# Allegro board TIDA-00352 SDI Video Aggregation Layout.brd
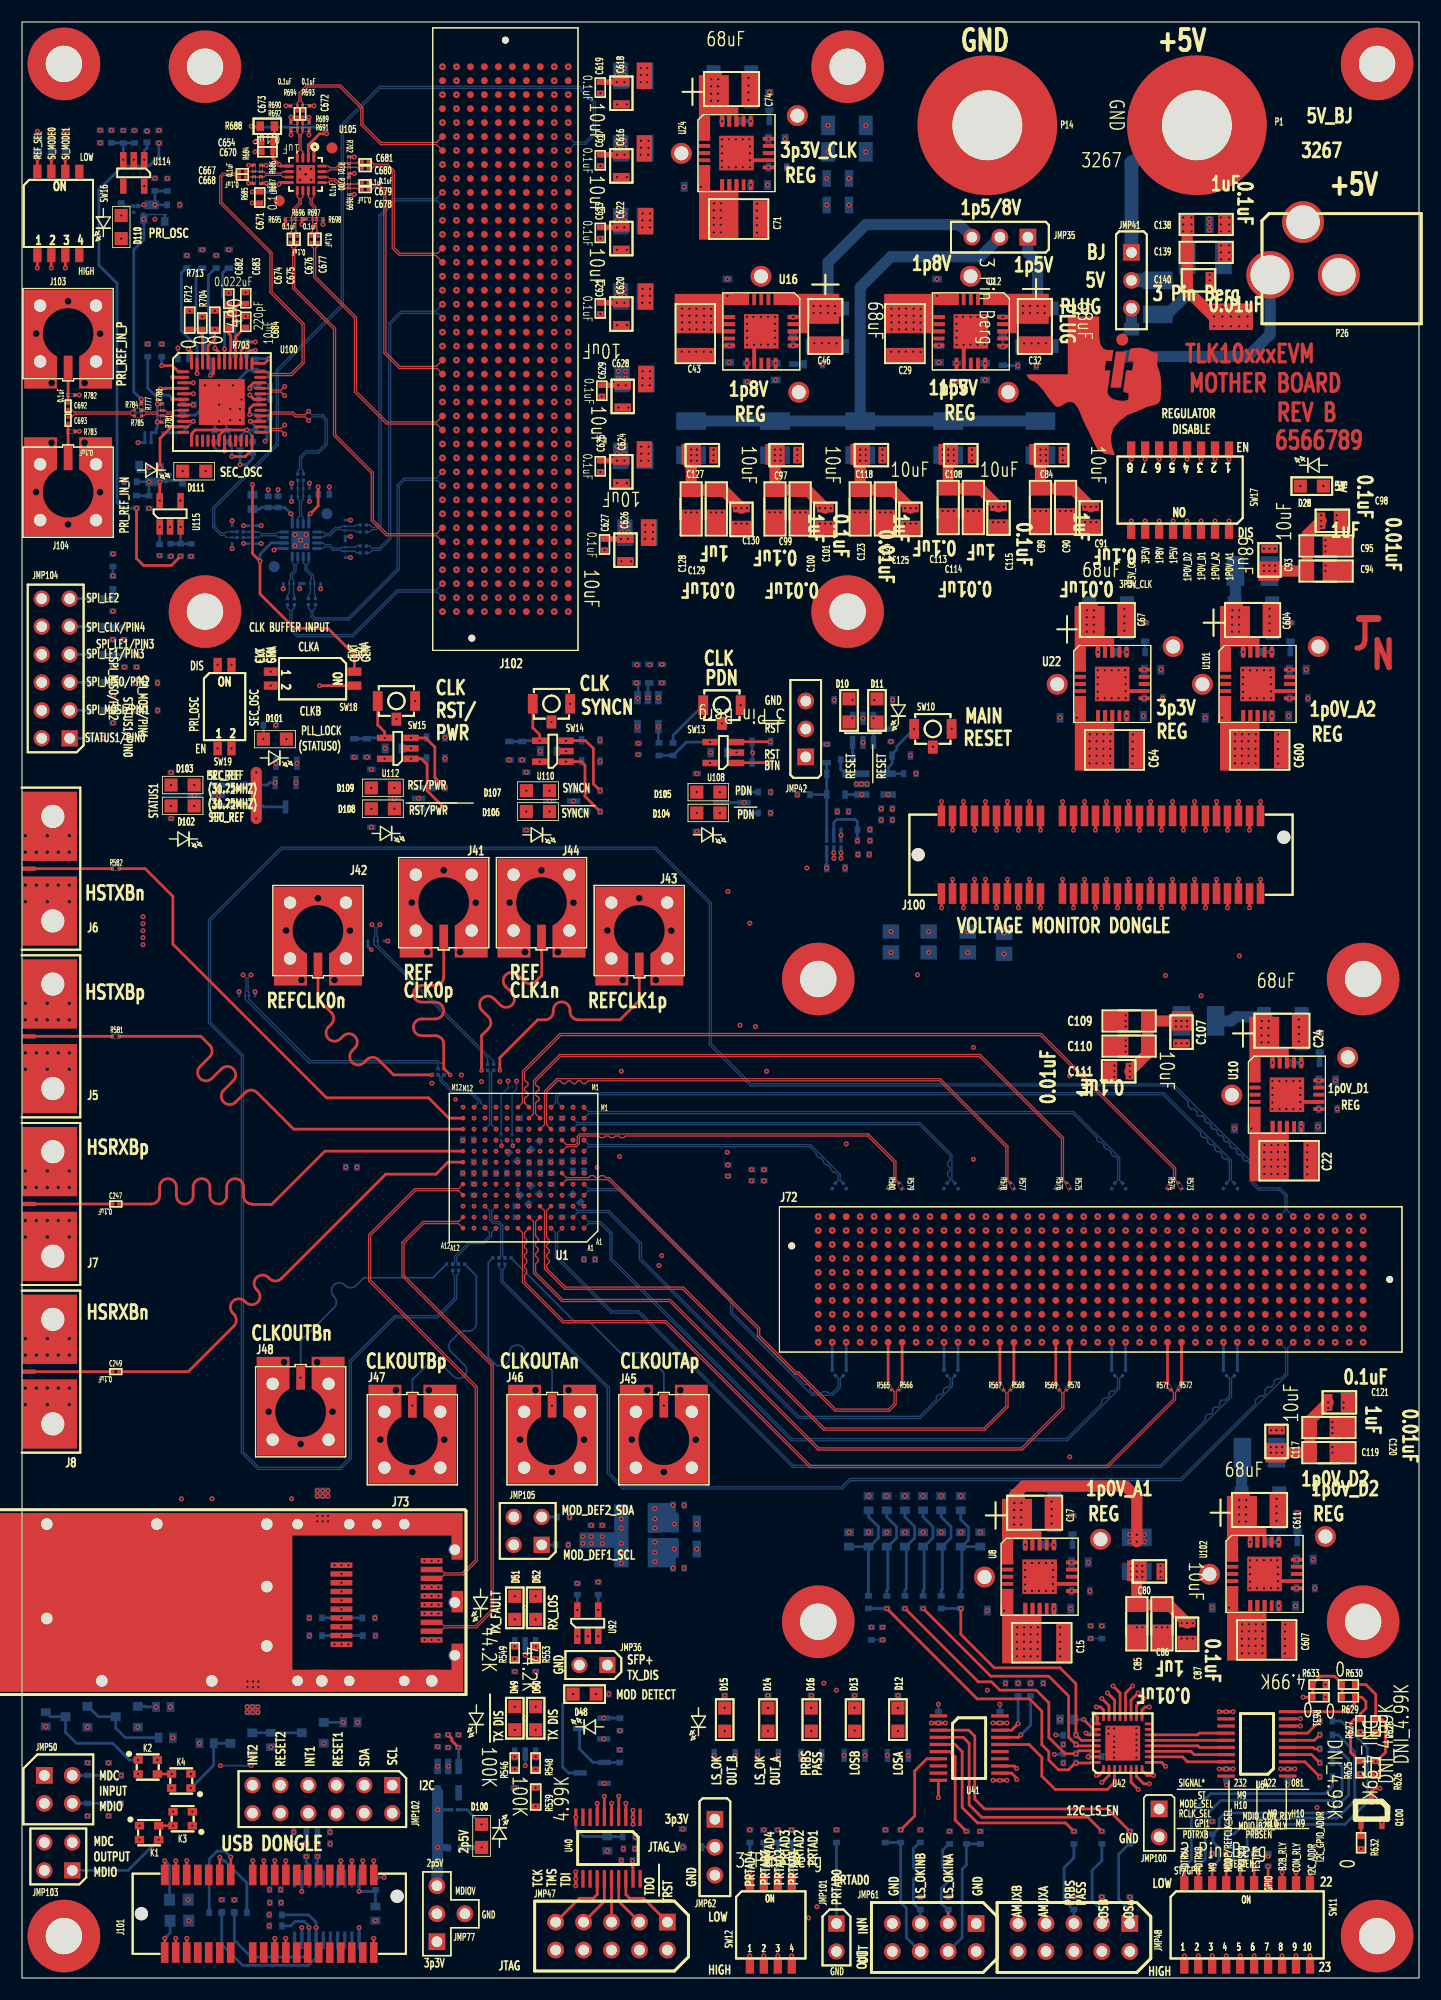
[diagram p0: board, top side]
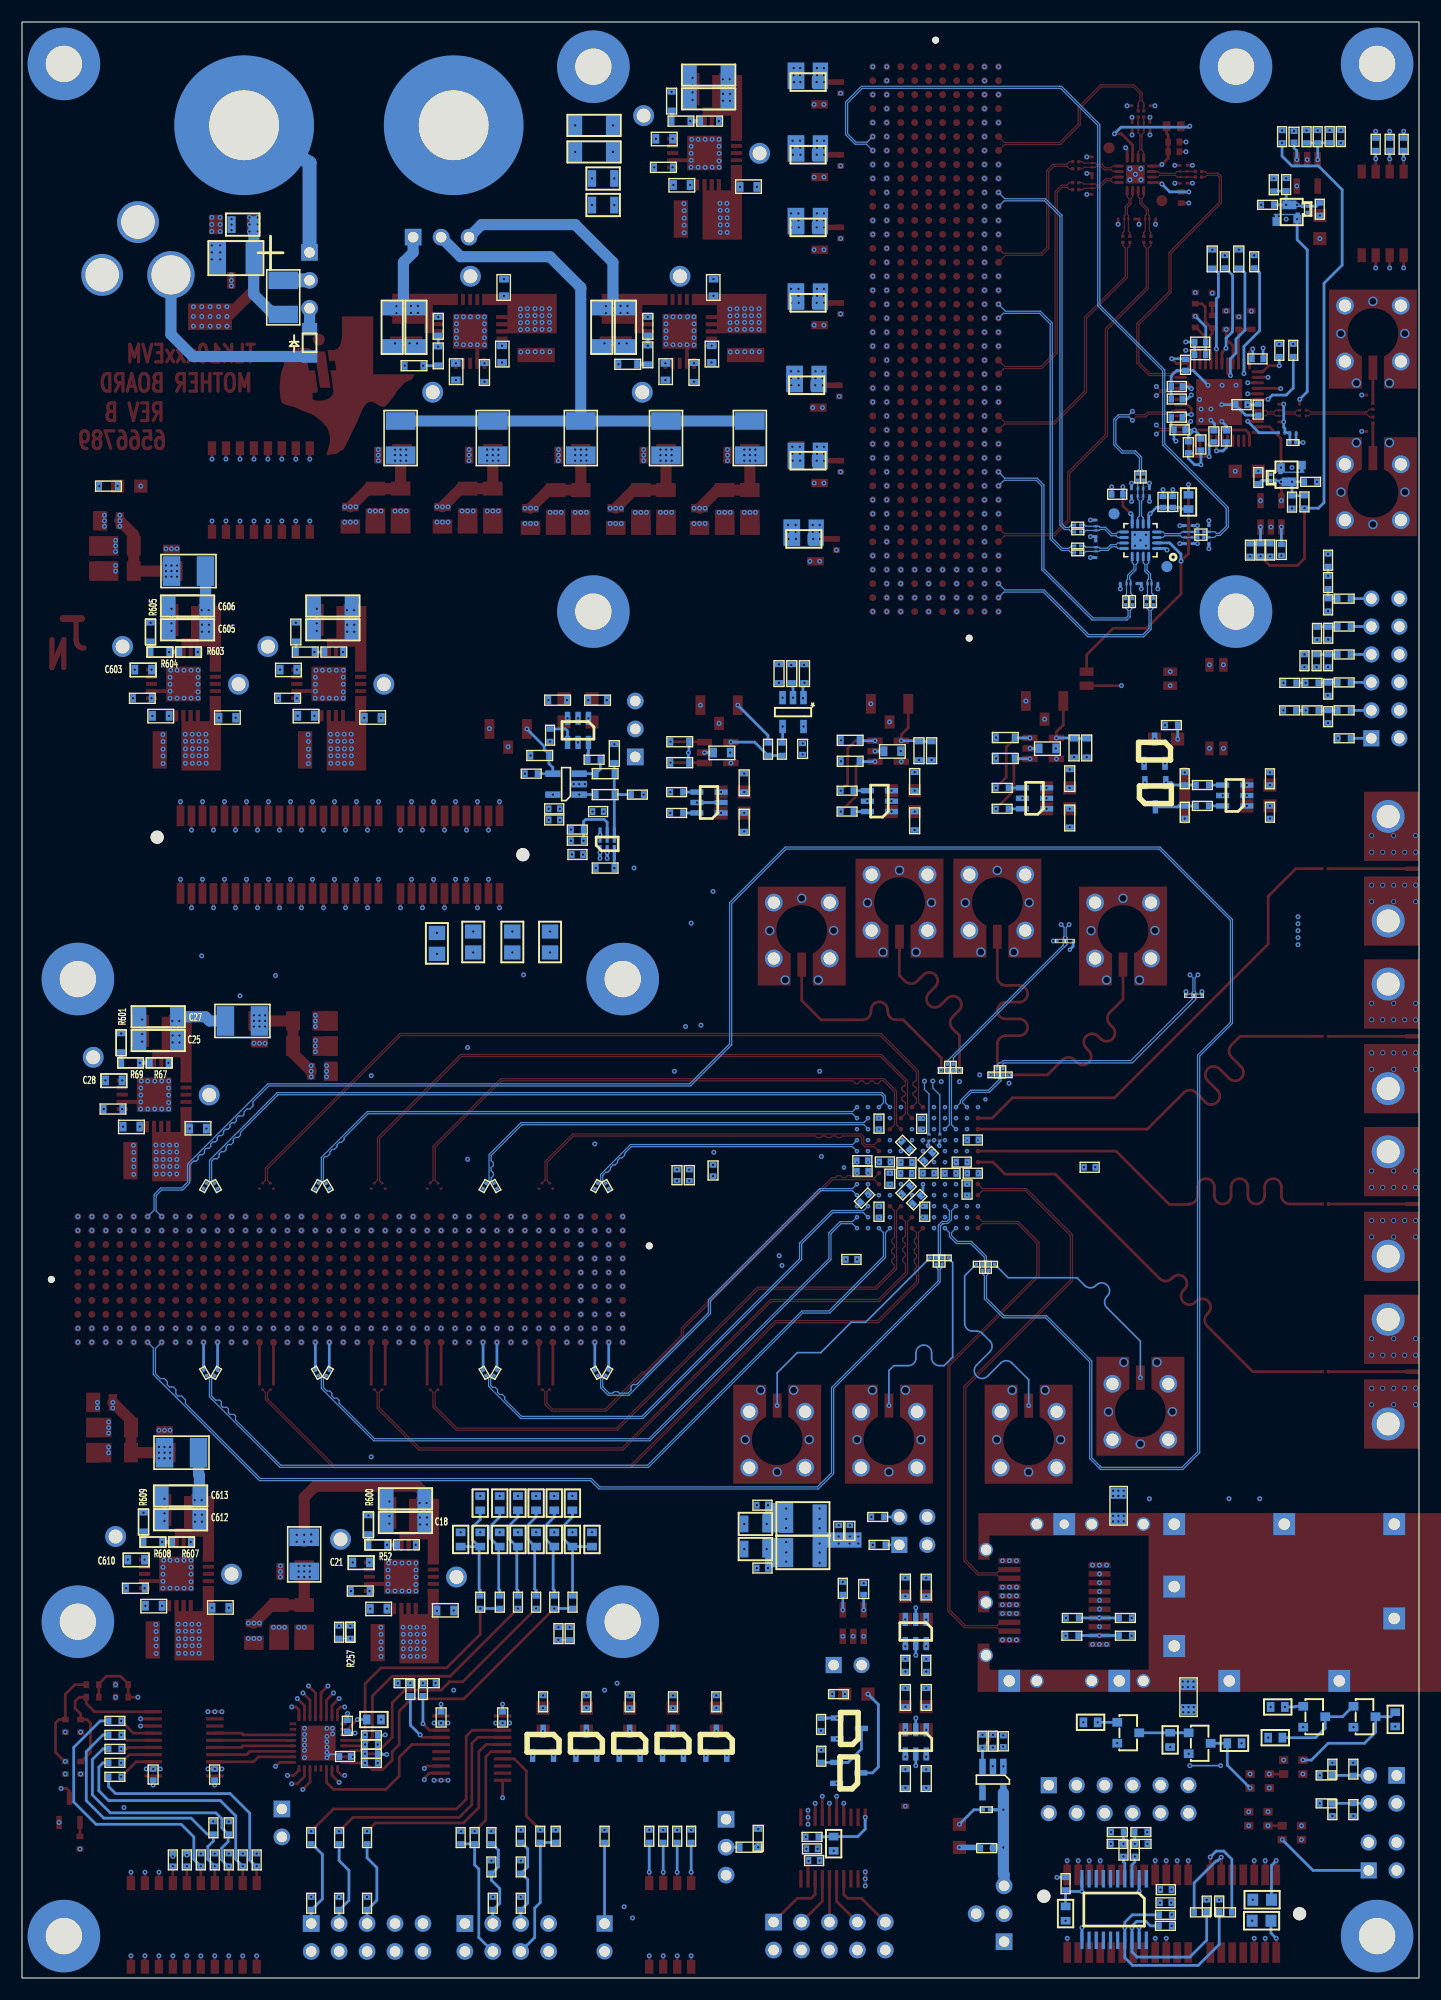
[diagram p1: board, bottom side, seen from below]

Outline 127 x 177.8 mm; copper layers: TOP, L2_GND, L3_SIG2, L4_GND, L5_PWR, L6_GND, L7_GND, L8_PWR, L9_GND, L10_PWR, L11_GND, L12_PWR, L13_GND, L14_SIG3, L15_GND, BOTTOM. Coordinates in mm from the lower left corner of the outline.
Outline path: rectangle 0,0 127,177.8

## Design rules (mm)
net group DIFF_CHA_CLKOUT_CONN: nets CHA_CLKOUTN_CONNECTOR CHA_CLKOUTP_CONNECTOR
net group DIFF_CLK0: nets REFCLK0N REFCLK0P
net group DIFF_CLK1: nets REFCLK1N REFCLK1P
net group DIFF_CLK_IN: nets CLKA_IN_N0 CLKA_IN_P0
net group DIFF_CLKA0: nets CLKA0N CLKA0P
net group DIFF_CLKA0_CON: nets CLKA0N_CON CLKA0P_CON
net group DIFF_CLKA1: nets CLKA1N CLKA1P
net group DIFF_CLKA1_CON: nets CLKA1N_CON CLKA1P_CON
net group DIFF_CLKA1_IN_CON: nets CLKA1N_IN_CON CLKA1P_IN_CON
net group DIFF_CLKA2: nets CLKA2N CLKA2P
net group DIFF_CLKA2_CON: nets CLKA2N_CON CLKA2P_CON
net group DIFF_CLKA3: nets CLKA3N CLKA3P
net group DIFF_CLKA_IN: nets CLKA_IN_N1 CLKA_IN_P1
net group DIFF_CLKA_IN_Y5: nets CLKA_IN_N_Y5N CLKA_IN_P_Y5P
net group DIFF_CLKB0: nets CLKB0N CLKB0P
net group DIFF_CLKB0N_CON: nets CLKB0N_CON CLKB0P_CON
net group DIFF_CLKB1: nets CLKB1N CLKB1P
net group DIFF_CLKB1_CON: nets CLKB1N_CON CLKB1P_CON
net group DIFF_CLKB1_IN_CON: nets CLKB1N_IN_CON CLKB1P_IN_CON
net group DIFF_CLKB2: nets CLKB2N CLKB2P
net group DIFF_CLKB2_CON: nets CLKB2N_CON CLKB2P_CON
net group DIFF_CLKB3: nets CLKB3N CLKB3P
net group DIFF_CLKB3N_CON: nets CLKA3N_CON CLKA3P_CON
net group DIFF_CLKB_IN: nets CLKB_IN_N1 CLKB_IN_P1
net group DIFF_CLKB_IN_Y7: nets CLKB_IN_N_Y7N CLKB_IN_P_Y7P
net group DIFF_CLKOUTA: nets CLKOUTAN CLKOUTAP
net group DIFF_CLKOUTB: nets CLKOUTBN CLKOUTBP
net group DIFF_DP1: nets CLKB3N_CON CLKB3P_CON
net group DIFF_INA0: nets INA0N INA0P
net group DIFF_INA1: nets INA1N INA1P
net group DIFF_INA2: nets INA2N INA2P
net group DIFF_INA3: nets INA3N INA3P
net group DIFF_INB0: nets A4N A4P
net group DIFF_INB1: nets A5N A5P
net group DIFF_INB2: nets A6N A6P
net group DIFF_INB3: nets A7N A7P
net group DIFF_JC_CLK0: nets REFCLK0N_U0N REFCLK0P_U0P
net group DIFF_JCCLK1: nets REFCLK1N_U1N REFCLK1P_U1P
net group DIFF_OUTA0: nets OUTA0N OUTA0P
net group DIFF_OUTA1: nets OUTA1N OUTA1P
net group DIFF_OUTA2: nets OUTA2N OUTA2P
net group DIFF_OUTA3: nets OUTA3N OUTA3P
net group DIFF_OUTB0: nets OUTA4N OUTA4P
net group DIFF_OUTB1: nets OUTA5N OUTA5P
net group DIFF_OUTB2: nets OUTA6N OUTA6P
net group DIFF_OUTB3: nets OUTA7N OUTA7P
net group DIFF_PRI_REF: nets PRI_REFN PRI_REFP
net group DIFF_PRI_REF_IN: nets PRI_REF_IN_N PRI_REF_IN_P
net group HSRXA: nets HSRXAN HSRXAP
net group HSTXA: nets HSTXAN HSTXAP
net group HIGH_SPEED: nets HSRXBN HSRXBP HSTXBN HSTXBP
net group HIGH_SPEED_SMA: nets HSRXBN_SMA HSRXBP_SMA HSTXBN_SMA HSTXBP_SMA
net group REFCLK_SMP: nets CLKOUTAN_SMA CLKOUTAP_SMA CLKOUTBN_SMA CLKOUTBP_SMA REFCLK0N_SMP REFCLK0P_SMP REFCLK1N_SMP REFCLK1P_SMP

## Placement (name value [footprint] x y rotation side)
C15  100uF  [CC1812]  92.71 30.48 0 top
C16  4.7uF  [CC0603]  89.28 33.4 180 bottom
C17  68uF  [CC1210]  90.42 42.29 0 top
C18  10uF  [CC1206]  90.42 41.4 0 bottom
C19  1uF  [CC0603]  93.81 33.57 0 bottom
C20  1uF  [CC1206]  90.42 43.56 0 bottom
C21  0.001uF  [CC0603]  95.41 37.77 0 bottom
C22  100uF  [CC1812]  115.19 74.3 0 top
C23  4.7uF  [CC0603]  111.76 77.22 180 bottom
C24  68uF  [CC1210]  112.9 86.11 0 top
C25  10uF  [CC1206]  112.9 85.22 0 bottom
C26  1uF  [CC0603]  116.29 77.39 0 bottom
C27  1uF  [CC1206]  112.9 87.38 0 bottom
C28  0.001uF  [CC0603]  117.89 81.59 0 bottom
C29  100uF  [CC1812]  80.26 149.48 270 top
C30  4.7uF  [CC0603]  83.19 152.91 90 bottom
C31  1uF  [CC0603]  83.36 148.38 270 bottom
C32  68uF  [CC1210]  92.08 151.76 270 top
C33  10uF  [CC1206]  91.19 151.76 270 bottom
C34  1uF  [CC1206]  93.34 151.76 270 bottom
C35  0.015uF  [CC0603]  87.56 146.78 270 bottom
C43  100uF  [CC1812]  61.21 149.48 270 top
C44  4.7uF  [CC0603]  64.14 152.91 90 bottom
C45  1uF  [CC0603]  64.31 148.38 270 bottom
C46  68uF  [CC1210]  73.03 151.76 270 top
C47  10uF  [CC1206]  72.14 151.76 270 bottom
C48  1uF  [CC1206]  74.3 151.76 270 bottom
C49  0.015uF  [CC0603]  68.51 146.78 270 bottom
C64  100uF  [CC1812]  99.31 111.63 0 top
C65  4.7uF  [CC0603]  95.89 114.55 180 bottom
C66  1uF  [CC0603]  100.42 114.73 0 bottom
C67  68uF  [CC1210]  97.03 123.44 0 top
C68  10uF  [CC1206]  97.03 122.56 0 bottom
C69  1uF  [CC1206]  97.03 124.71 0 bottom
C70  10pF  [CC0603]  102.02 118.93 0 bottom
C71  100uF  [CC1812]  65.15 159.89 0 top
C72  4.7uF  [CC0603]  61.72 162.81 180 bottom
C73  1uF  [CC0603]  66.25 162.99 0 bottom
C74  68uF  [CC1210]  62.87 171.7 0 top
C75  10uF  [CC1206]  62.87 170.81 0 bottom
C76  1uF  [CC1206]  62.87 172.97 0 bottom
C77  10pF  [CC0603]  67.85 167.19 0 bottom
C80  10uF  [CC0805]  101.47 36.96 0 top
C84  10uF  [CC0805]  92.58 138.43 0 top
C85  1uF  [CC1206]  101.35 33.91 270 top
C86  0.1uF  [CC1206]  103.63 33.91 270 top
C87  0.01uF  [CC0805]  105.92 32.26 270 top
C89  1uF  [CC1206]  92.58 135.38 270 top
C90  0.1uF  [CC1206]  94.87 135.38 270 top
C91  0.01uF  [CC0805]  97.16 133.73 270 top
C93  10uF  [CC0805]  113.41 127.89 90 top
C94  1uF  [CC1206]  116.84 127.89 0 top
C95  0.1uF  [CC1206]  116.84 130.18 0 top
C97  10uF  [CC0805]  68.45 138.43 0 top
C98  0.01uF  [CC0805]  118.11 132.46 0 top
C99  1uF  [CC1206]  68.45 135.25 270 top
C100  0.1uF  [CC1206]  70.74 135.25 270 top
C101  0.01uF  [CC0805]  73.03 133.6 270 top
C107  10uF  [CC0805]  105.41 87 270 top
C108  10uF  [CC0805]  84.33 138.43 0 top
C109  1uF  [CC1206]  102.36 87 180 top
C110  0.1uF  [CC1206]  102.36 84.71 180 top
C111  0.01uF  [CC0805]  100.71 82.42 180 top
C113  1uF  [CC1206]  84.2 135.38 270 top
C114  0.1uF  [CC1206]  86.49 135.38 270 top
C115  0.01uF  [CC0805]  88.77 133.73 270 top
C117  10uF  [CC0805]  114.05 47.75 90 top
C118  10uF  [CC0805]  76.2 138.43 0 top
C119  1uF  [CC1206]  117.09 47.75 0 top
C120  0.1uF  [CC1206]  117.09 50.04 0 top
C121  0.01uF  [CC0805]  118.75 52.32 0 top
C123  1uF  [CC1206]  76.2 135.25 270 top
C124  0.1uF  [CC1206]  78.49 135.25 270 top
C125  0.01uF  [CC0805]  80.77 133.6 270 top
C127  10uF  [CC0805]  60.83 138.43 0 top
C128  1uF  [CC1206]  60.83 135.25 270 top
C129  0.1uF  [CC1206]  63.12 135.25 270 top
C130  0.01uF  [CC0805]  65.41 133.6 270 top
C136  68uF  [CC1210]  105.92 156.34 0 bottom
C137  10uF  [CC0805]  105.92 159.38 0 bottom
C138  1uF  [CC1206]  105.94 159.4 0 top
C139  0.1uF  [CC1206]  105.94 156.86 0 top
C140  0.01uF  [CC0805]  105.94 154.32 0 top
C141  0.1uF  [CC0402]  41.12 73.18 180 bottom
C142  0.1uF  [CC0402]  42.13 74.18 180 bottom
C143  0.1uF  [CC0402]  49.99 71.27 315 bottom
C144  0.1uF  [CC0402]  50.05 74.27 0 bottom
C145  0.1uF  [CC0402]  50.03 73.32 0 bottom
C146  0.1uF  [CC0402]  64.16 73.96 270 bottom
C147  0.1uF  [CC0402]  44.91 70.21 270 bottom
C148  0.1uF  [CC0402]  45.24 77.09 90 bottom
C149  0.1uF  [CC0402]  30.5 73.71 180 bottom
C150  0.1uF  [CC0402]  49.08 70.21 270 bottom
C151  0.1uF  [CC0402]  48 74.16 0 bottom
C152  0.1uF  [CC0402]  48.09 73.21 270 bottom
C153  0.1uF  [CC0402]  43.15 73.16 180 bottom
C163  0.1uF  [CC0402]  41.07 72.22 270 bottom
C164  0.1uF  [CC0402]  46.28 75.28 45 bottom
C165  0.1uF  [CC0402]  44.21 75.04 315 bottom
C166  0.1uF  [CC0402]  46.06 73.12 0 bottom
C167  0.1uF  [CC0402]  46.22 72.03 315 bottom
C168  0.1uF  [CC0402]  52.15 65.33 180 bottom
C169  0.1uF  [CC0402]  49.11 77.11 90 bottom
C170  0.1uF  [CC0402]  45.14 73.18 180 bottom
C171  0.1uF  [CC0402]  46.04 74.11 0 bottom
C172  0.1uF  [CC0402]  45.25 71.13 315 bottom
C173  0.1uF  [CC0402]  66.32 73.53 270 bottom
C174  0.1uF  [CC0402]  67.44 73.53 270 bottom
C188  0.1uF  [CC0402]  41.12 76.19 180 bottom
C189  0.1uF  [CC0402]  79.17 106.3 180 bottom
C190  1uF  [CC0402]  79.17 105.28 180 bottom
C191  DNI_0.1uF  [CC0201]  38.36 82.09 0 bottom
C192  0.1uF  [CC0201]  43.9 65.46 0 bottom
C193  0.1uF  [CC0201]  38.36 82.66 270 bottom
C194  DNI_0.1uF  [CC0201]  43.9 65.46 270 bottom
C195  0.1uF  [CC0201]  37.82 82.66 270 bottom
C196  DNI_0.1uF  [CC0201]  43.36 65.46 270 bottom
C197  DNI_0.1uF  [CC0201]  37.82 82.09 180 bottom
C198  0.1uF  [CC0201]  43.36 65.46 180 bottom
C199  0.1uF  [CC0201]  42.87 82.5 0 bottom
C200  0.1uF  [CC0201]  39.69 64.89 0 bottom
C201  DNI_0.1uF  [CC0201]  42.87 83.06 270 bottom
C202  DNI_0.1uF  [CC0201]  39.69 64.89 270 bottom
C203  DNI_0.1uF  [CC0201]  42.33 83.06 270 bottom
C204  DNI_0.1uF  [CC0201]  39.15 64.89 270 bottom
C205  0.1uF  [CC0201]  42.33 82.5 180 bottom
C206  0.1uF  [CC0201]  39.15 64.89 180 bottom
C210  0.1uF  [CC0201]  74.65 54.76 60 bottom
C211  0.1uF  [CC0201]  109.5 72.24 240 bottom
C212  0.1uF  [CC0201]  73.94 54.76 120 bottom
C213  0.1uF  [CC0201]  110.21 72.24 300 bottom
C214  0.1uF  [CC0201]  84.81 54.76 60 bottom
C215  0.1uF  [CC0201]  99.34 72.24 240 bottom
C216  0.1uF  [CC0201]  84.1 54.76 120 bottom
C217  0.1uF  [CC0201]  100.05 72.24 300 bottom
C218  0.1uF  [CC0201]  100.05 54.76 60 bottom
C219  0.1uF  [CC0201]  84.1 72.24 240 bottom
C220  0.1uF  [CC0201]  99.34 54.76 120 bottom
C221  0.1uF  [CC0201]  84.81 72.24 300 bottom
C222  0.1uF  [CC0201]  110.21 54.76 60 bottom
C223  0.1uF  [CC0201]  73.94 72.24 240 bottom
C224  0.1uF  [CC0201]  109.5 54.76 120 bottom
C225  0.1uF  [CC0201]  74.65 72.24 300 bottom
C247  0.1uF  [CC0201]  8.8 70.36 180 top
C249  0.1uF  [CC0201]  8.8 55.12 180 top
C274  1uF  [CC0402]  115.06 19.05 270 bottom
C275  1uF  [CC0402]  109.47 19.05 270 bottom
C278  1uF  [CC0402]  88.92 23.12 90 bottom
C279  1uF  [CC0402]  83.32 23.12 90 bottom
C280  1uF  [CC0402]  97.44 22.37 90 bottom
C281  1uF  [CC0402]  97.07 20.12 0 bottom
C282  1uF  [CC0402]  75.95 102.11 0 bottom
C283  1uF  [CC0402]  75.18 106.05 180 bottom
C286  1uF  [CC0402]  23.57 8.05 180 bottom
C295  0.1uF  [CC0402]  52.77 40.08 90 bottom
C296  22uF  [CC0805]  59.31 41.27 0 bottom
C297  0.1uF  [CC0402]  59.13 42.96 0 bottom
C298  0.1uF  [CC0402]  50.5 34.8 90 bottom
C299  0.1uF  [CC0402]  51.76 40.08 90 bottom
C300  22uF  [CC0805]  59.31 38.99 0 bottom
C301  0.1uF  [CC0402]  59.13 37.25 0 bottom
C302  1uF  [CC0402]  23.6 6.86 180 bottom
C303  1uF  [CC0402]  55.55 10.69 180 bottom
C304  1uF  [CC0402]  55.74 11.76 180 bottom
C600  100uF  [CC1812]  112.52 111.63 0 top
C601  4.7uF  [CC0603]  109.09 114.55 180 bottom
C602  1uF  [CC0603]  113.62 114.73 0 bottom
C603  0.001uF  [CC0603]  115.22 118.93 0 bottom
C604  68uF  [CC1210]  110.24 123.44 0 top
C605  10uF  [CC1206]  110.24 122.56 0 bottom
C606  1uF  [CC1206]  110.24 124.71 0 bottom
C607  100uF  [CC1812]  113.16 30.73 0 top
C608  4.7uF  [CC0603]  109.73 33.66 180 bottom
C609  1uF  [CC0603]  114.26 33.83 0 bottom
C610  0.001uF  [CC0603]  115.86 38.03 0 bottom
C611  68uF  [CC1210]  110.87 42.55 0 top
C612  10uF  [CC1206]  110.87 41.66 0 bottom
C613  1uF  [CC1206]  110.87 43.81 0 bottom
C614  1uF  [CC0402]  37.8 20.96 90 bottom
C615  1uF  [CC0201]  39.05 15.3 0 bottom
C616  10uF  [CC0805]  54.48 165.74 270 top
C617  0.1uF  [CC0402]  52.59 165.79 270 top
C618  10uF  [CC0805]  54.48 172.34 270 top
C619  0.1uF  [CC0402]  52.59 172.39 270 top
C620  10uF  [CC0805]  54.48 152.27 270 top
C621  0.1uF  [CC0402]  52.59 152.32 270 top
C622  10uF  [CC0805]  54.48 159.13 270 top
C623  0.1uF  [CC0402]  52.59 159.18 270 top
C624  10uF  [CC0805]  54.48 137.92 270 top
C625  0.1uF  [CC0402]  52.59 137.97 270 top
C626  10uF  [CC0805]  54.86 130.81 270 top
C627  0.1uF  [CC0402]  52.97 130.86 270 top
C628  10uF  [CC0805]  54.61 144.78 270 top
C629  0.1uF  [CC0402]  52.72 144.83 270 top
C630  10uF  [CC0805]  73.15 161.16 0 bottom
C631  1uF  [CC1206]  73.28 168.4 0 bottom
C632  0.1uF  [CC1206]  73.28 165.99 0 bottom
C633  0.01uF  [CC0805]  73.15 163.58 0 bottom
C634  10uF  [0805]  78.99 95.12 270 bottom
C635  10uF  [0805]  85.98 95.12 270 bottom
C636  10uF  [0805]  89.28 95 270 bottom
C637  10uF  [0805]  82.42 95.12 270 bottom
C638  0.1uF  [CC0402]  21.21 147.19 270 bottom
C639  0.1uF  [CC0402]  20.45 147.57 180 bottom
C640  0.1uF  [CC0402]  20.45 148.72 180 bottom
C641  0.1uF  [CC0402]  14.61 143.13 270 bottom
C642  0.1uF  [CC0402]  15.58 143 0 bottom
C643  0.1uF  [CC0402]  15.24 147.19 180 bottom
C644  0.1uF  [CC0402]  19.81 139.95 270 bottom
C645  0.1uF  [CC0402]  21.21 140.72 0 bottom
C646  0.1uF  [CC0402]  21.46 141.86 0 bottom
C647  0.1uF  [CC0402]  20.95 139.7 270 bottom
C648  0.1uF  [CC0402]  21.46 144.65 0 bottom
C649  0.1uF  [CC0402]  17.53 139.57 90 bottom
C650  0.1uF  [CC0402]  18.67 139.57 90 bottom
C651  0.1uF  [CC0402]  21.46 143.51 0 bottom
C652  0.1uF  [CC0201]  25.07 136.16 90 bottom
C653  0.1uF  [CC0201]  25.58 136.16 90 bottom
C654  1uF  [CC0402]  22.86 166.88 180 top
C655  0.1uF  [CC0402]  23.29 133.62 90 bottom
C656  0.1uF  [CC0402]  27.99 134.89 180 bottom
C657  0.1uF  [CC0201]  20.12 130.95 180 bottom
C658  0.1uF  [CC0201]  20.12 131.46 180 bottom
C659  0.1uF  [CC0201]  30.74 132.08 0 bottom
C660  0.1uF  [CC0201]  31.3 131.44 180 bottom
C661  0.1uF  [CC0201]  30.74 130.18 0 bottom
C662  0.1uF  [CC0201]  31.3 129.54 180 bottom
C663  0.1uF  [CC0201]  26.67 125.39 270 bottom
C664  0.1uF  [CC0201]  26.04 124.83 90 bottom
C665  0.1uF  [CC0201]  24.77 125.39 270 bottom
C666  0.1uF  [CC0201]  24.13 124.83 90 bottom
C667  0.1uF  [CC0201]  20.32 164.21 180 top
C668  0.1uF  [CC0201]  20.32 163.7 180 top
C669  1uF  [CC0402]  22.4 133.62 90 bottom
C670  0.1uF  [CC0402]  22.86 165.99 180 top
C671  0.1uF  [CC0402]  21.59 161.29 90 top
C672  0.1uF  [CC0201]  25.53 169.16 90 top
C673  0.1uF  [CC0201]  25.02 169.16 90 top
C674  0.1uF  [CC0201]  24.38 158.33 270 top
C675  0.1uF  [CC0201]  25.02 157.77 90 top
C676  0.1uF  [CC0201]  26.29 158.33 270 top
C677  0.1uF  [CC0201]  26.92 157.77 90 top
C678  0.1uF  [CC0201]  30.92 162.56 0 top
C679  0.1uF  [CC0201]  31.48 163.19 180 top
C680  0.1uF  [CC0201]  30.92 164.47 0 top
C681  0.1uF  [CC0201]  31.48 165.1 180 top
C682  0.022uF  [CC0402]  18.78 152.1 90 top
C683  220pF  [CC0402]  20.32 152.15 90 top
C684  10uF  [CC0402]  20.32 149.99 90 top
C685  1uF  [CC0402]  56.02 112.28 270 bottom
C686  0.1uF  [CC0603]  62.61 111.39 0 bottom
C687  0.1uF  [CC0603]  47.12 111.52 0 bottom
C688  0.1uF  [CC0603]  33.02 111.77 0 bottom
C689  1uF  [CC0402]  11.38 166.81 90 bottom
C690  1uF  [CC0201]  10.16 161.06 270 bottom
C691  0.1uF  [CC0201]  11.18 139.57 0 bottom
C692  0.1uF  [CC0201]  4.19 142.6 90 top
C693  0.1uF  [CC0201]  4.19 141.88 270 top
C694  1uF  [CC0402]  12.5 130.37 270 bottom
C695  1uF  [CC0201]  13.46 136.12 90 bottom
D9  BAT60A 10V, 3A  [SOD323]  100.86 148.63 270 bottom
D10  RED  [LED_HSMB_C170DRA]  75.18 114.17 90 top
D11  GREEN  [LED_HSMB_C170DRA]  77.72 114.17 90 top
D12  RED  [LED_HSMB_C170DRA]  79.63 22.44 90 top
D13  RED  [LED_HSMB_C170DRA]  75.69 22.44 90 top
D14  GREEN  [LED_HSMB_C170DRA]  67.82 22.44 90 top
D15  GREEN  [LED_HSMB_C170DRA]  63.88 22.44 90 top
D16  GREEN  [LED_HSMB_C170DRA]  71.75 22.44 90 top
D28  BLUE  [LED_HSMB_C170DRA]  116.2 135.61 0 top
D48  ORANGE  [LED_HSMB_C170DRA]  50.1 25.81 0 top
D49  GREEN  [LED_HSMB_C170DRA]  44.8 22.56 90 top
D50  RED  [LED_HSMB_C170DRA]  46.7 22.56 90 top
D51  RED  [LED_HSMB_C170DRA]  44.8 32.6 90 top
D52  YELLOW  [LED_HSMB_C170DRA]  46.7 32.6 90 top
D100  GREEN  [LED_HSMB_C170DRA]  41.78 13.97 270 top
D101  GREEN  [LED_HSMB_C170DRA]  24.04 112.62 180 top
D102  GREEN  [LED_HSMB_C170DRA]  15.65 106.54 180 top
D103  YELLOW  [LED_HSMB_C170DRA]  15.65 108.44 180 top
D104  GREEN  [LED_HSMB_C170DRA]  63.45 105.9 180 top
D105  RED  [LED_HSMB_C170DRA]  63.45 107.8 180 top
D106  GREEN  [LED_HSMB_C170DRA]  47.95 106.03 180 top
D107  RED  [LED_HSMB_C170DRA]  47.95 107.93 180 top
D108  GREEN  [LED_HSMB_C170DRA]  33.86 106.28 180 top
D109  RED  [LED_HSMB_C170DRA]  33.86 108.18 180 top
D110  GREEN  [LED_HSMB_C170DRA]  9.02 158.11 90 top
D111  ORANGE  [LED_HSMB_C170DRA]  16.71 136.97 180 top
J5  HSTXBP  [CON_32K243-40M]  0.6 85.6 90 top
J6  HSTXBN  [CON_32K243-40M]  0.6 100.84 90 top
J7  HSRXBP  [CON_32K243-40M]  0.6 70.36 90 top
J8  HSRXBN  [CON_32K243-40M]  0.6 55.12 90 top
J41  REFCLK0P  [32K141-40M-FR4WVIA]  38.34 97.75 0 top
J42  REFCLK0N  [32K141-40M-FR4WVIA]  26.91 95.21 0 top
J43  REFCLK1P  [32K141-40M-FR4WVIA]  56.12 95.21 0 top
J44  REFCLK1N  [32K141-40M-FR4WVIA]  47.23 97.75 0 top
J45  CLKOUTAP  [32K141-40M-FR4WVIA]  58.35 48.93 180 top
J46  CLKOUTAN  [32K141-40M-FR4WVIA]  48.19 48.93 180 top
J47  CLKOUTBP  [32K141-40M-FR4WVIA]  35.49 48.93 180 top
J48  CLKOUTBN  [32K141-40M-FR4WVIA]  25.33 51.47 180 top
J72  SEAF_ASP-134486-01  [ASP-134486]  97.16 63.5 180 top
J73  SFP_PLUS_CONN_WITH_CAGE  [AMP_SFPCAGE_WIDECHANNEL]  32.25 34.13 0 top
J100  MEC1-130-02-F-D-A Connector  [MEC1-130-02-F-D-A]  93.09 102.11 0 top
J101  MEC1-120-02-F-D-A Connector  [MEC1-120-02-F-D-A]  22.48 5.84 0 top
J102  SEAF_ASP-134486-01  [ASP-134486]  43.94 148.97 270 top
J103  PRI_REF_IN_P  [32K141-40M-FR4WVIA]  4.19 149.48 0 top
J104  PRI_REF_IN_N  [32K141-40M-FR4WVIA]  4.19 135.06 180 top
JMP35  3 Pin Berg  [BERG3]  91.44 158.24 270 top
JMP36  Header 1x2  [HDR_THVT_1X2_100]  53.21 28.45 270 top
JMP41  3 Pin Berg  [BERG3]  100.86 156.86 0 top
JMP42  3 Pin Berg  [BERG3]  71.25 111 180 top
JMP47  Header 5x2  [BERG2X5]  58.67 5.08 270 top
JMP48  Header 5x2  [BERG2X5]  100.71 4.95 270 top
JMP50  Header 2x2  [BERG2X2]  2.03 18.41 0 top
JMP61  Header 4x2  [BERG2X4]  86.74 4.95 270 top
JMP62  3 Pin Berg  [BERG3]  62.99 14.43 0 top
JMP77  Header T 4pin  [BERG2X3TEE]  37.72 3.3 90 top
JMP100  2 Pin Berg  [BERG2]  103.38 15.37 0 top
JMP101  Header 2x1  [HDR_THVT_1X2_100]  74.04 4.95 0 top
JMP102  Header 2x6  [HDR_THVT_2X6_100]  33.66 17.53 270 top
JMP103  Header 2x2  [HDR_THVT_2X2_100]  4.57 9.78 180 top
JMP104  Header 6x2  [HDR_THVT_2X6_100]  4.33 112.69 180 top
JMP105  Header 2x2  [HDR_THVT_2X2_100]  47.24 39.37 180 top
K1  AQY221R2T  [PANASONIC_AQY221R2T_VSSOP]  11.56 13.21 0 top
K2  AQY221R2T  [PANASONIC_AQY221R2T_VSSOP]  11.43 19.18 0 top
K3  AQY221R2T  [PANASONIC_AQY221R2T_VSSOP]  14.61 14.48 180 top
K4  AQY221R2T  [PANASONIC_AQY221R2T_VSSOP]  14.48 17.91 180 top
L1  Ferrite Bead_1210  [R1210]  101.35 38.51 270 bottom
L2  Ferrite Bead_1210  [R1210]  92.58 139.98 270 bottom
L3  Ferrite Bead_1210  [R1210]  111.86 127.89 0 bottom
L4  Ferrite Bead_1210  [R1210]  68.45 139.98 270 bottom
L5  Ferrite Bead_1210  [R1210]  106.96 87 180 bottom
L6  Ferrite Bead_1210  [R1210]  84.2 139.98 270 bottom
L7  Ferrite Bead_1210  [R1210]  112.5 47.75 0 bottom
L8  Ferrite Bead_1210  [R1210]  76.2 139.98 270 bottom
L9  Ferrite Bead_1210  [R1210]  60.83 139.98 270 bottom
L14  Ferrite Bead_1210  [R1210]  103.25 152.77 270 bottom
L15  4.7uH  [1210]  56.01 41.73 180 bottom
L16  4.7uH  [1210]  56.01 38.68 180 bottom
L100  BLM15HD102SN1D  [0603]  56.39 165.74 180 bottom
L101  BLM15HD102SN1D  [0603]  56.39 172.34 180 bottom
L102  BLM15HD102SN1D  [0603]  56.39 152.27 180 bottom
L103  BLM15HD102SN1D  [0603]  56.39 159.13 180 bottom
L104  BLM15HD102SN1D  [0603]  56.39 137.92 180 bottom
L105  BLM15HD102SN1D  [0603]  56.77 130.81 180 bottom
L106  BLM15HD102SN1D  [0603]  56.52 144.78 180 bottom
NOREF  -  []  0 177.8 0 top
NOREF#2  -  [unnamed#2]  123.19 3.81 0 top
NOREF#3  -  [unnamed#2]  3.81 3.81 0 top
NOREF#4  -  [unnamed#2]  3.81 173.99 0 top
NOREF#5  -  []  -91.57 -261.77 0 top
NOREF#6  -  []  127 0 90 top
NOREF#7  -  [unnamed#2]  123.19 173.99 0 top
NOREF#8  -  []  31.62 17.53 0 top
NOREF#9  -  []  515.24 -160.15 0 top
NOREF#10  -  []  92.96 186.94 0 top
P1  5V_BJ  [BJACK]  106.81 168.41 0 top
P14  GND  [BJACK]  87.76 168.41 0 top
P26  RAPC722  [CON_RAPC722_JACK_THVT_3]  116.59 154.81 90 top
Q3  FDV301N  [SOT23]  79.63 21.34 270 bottom
Q4  FDV301N  [SOT23]  75.69 21.34 270 bottom
Q5  FDV301N  [SOT23]  67.82 21.34 270 bottom
Q6  FDV301N  [SOT23]  71.75 21.34 270 bottom
Q7  FDV301N  [SOT23]  63.88 21.34 270 bottom
Q11  FDV301N  [SOT23]  51.79 22.68 0 bottom
Q12  FDV301N  [SOT23]  51.84 18.64 0 bottom
Q100  FDV301N  [SOT23]  122.68 15.24 270 top
Q101  FDV301N  [FAIRCHILD_NFET_FDV301N]  4.95 23.75 180 bottom
Q102  FDV301N  [FAIRCHILD_NFET_FDV301N]  9.53 23.75 180 bottom
Q103  FDV301N  [FAIRCHILD_NFET_FDV301N]  19.94 21.34 180 bottom
Q104  FDV301N  [FAIRCHILD_NFET_FDV301N]  26.43 22.29 180 bottom
Q105  FDV301N  [SOT23]  24.04 111.52 270 bottom
Q106  FDV301N  [SOT23]  23.96 107.56 90 bottom
R49  4.99K  [R0603]  97.09 35.17 180 bottom
R50  1.13K  [R0603]  91.21 39.38 0 bottom
R52  4.02K  [R0603]  95.49 39.38 180 bottom
R66  4.99K  [R0603]  119.57 78.99 180 bottom
R67  1.13K  [R0603]  113.69 83.19 0 bottom
R69  4.02K  [R0603]  117.97 83.19 180 bottom
R83  4.99K  [R0603]  84.96 145.1 90 bottom
R84  4.12K  [R0603]  89.16 150.98 270 bottom
R86  4.53K  [R0603]  89.16 148.29 270 bottom
R117  4.99K  [R0603]  65.91 145.1 90 bottom
R118  3.57K  [R0603]  70.11 150.98 270 bottom
R120  2.8K  [R0603]  70.11 146.7 90 bottom
R168  4.99K  [R0603]  103.69 116.33 180 bottom
R169  3.57K  [R0603]  97.82 120.53 0 bottom
R171  1.13K  [R0603]  102.09 120.53 180 bottom
R185  4.99K  [R0603]  69.53 164.59 180 bottom
R186  3.57K  [R0603]  63.65 168.79 0 bottom
R188  1.13K  [R0603]  67.93 168.79 180 bottom
R239  4.99K  [R0603]  74.83 100.89 180 bottom
R240  DNI_4.99K  [R0402]  75.95 103.38 0 bottom
R241  4.99K  [R0603]  73.15 112.14 270 bottom
R242  130  [R0603]  73.84 116.15 0 bottom
R243  49.9  [R0603]  73.15 107.57 0 bottom
R244  100K  [R0603]  73.15 109.47 0 bottom
R245  4.99K  [R0402]  77.09 104.39 180 bottom
R246  130  [R0603]  79.15 116.15 180 bottom
R247  49.9K  [R0402]  105.66 11.3 270 bottom
R248  49.9K  [R0402]  106.93 11.3 270 bottom
R249  49.9K  [R0402]  108.2 11.3 270 bottom
R250  49.9K  [R0402]  109.47 11.3 270 bottom
R251  49.9K  [R0402]  110.74 11.3 270 bottom
R252  49.9K  [R0402]  112.01 11.3 270 bottom
R253  49.9K  [R0402]  113.28 11.3 270 bottom
R254  49.9K  [R0402]  84.2 7.37 270 bottom
R255  49.9K  [R0402]  81.66 7.37 270 bottom
R256  DNI_4.99K  [R0402]  77.22 30.73 90 bottom
R257  DNI_4.99K  [R0402]  97.16 30.86 90 bottom
R258  20K  [R0402]  75.56 110.74 180 bottom
R259  20K  [R0402]  78.99 113.54 270 bottom
R262  DNI_4.99K  [R0402]  78.23 30.73 90 bottom
R263  DNI_4.99K  [R0402]  98.17 30.86 90 bottom
R268  DNI_0  [R0603]  60.07 13.54 270 bottom
R269  0  [R0603]  60.07 11.89 0 bottom
R270  4.99K  [R0402]  55.75 12.83 180 bottom
R273  0  [R0402]  100.71 6.22 90 bottom
R274  0  [R0402]  87.12 12.19 90 bottom
R275  0  [R0402]  95.63 6.22 90 bottom
R276  0  [R0402]  100.71 12.19 90 bottom
R277  0  [R0402]  78.49 12.32 90 bottom
R278  250  [R0402]  79.63 25.68 270 bottom
R279  0  [R0402]  98.17 6.22 90 bottom
R280  250  [R0402]  75.69 25.68 270 bottom
R281  250  [R0402]  67.82 25.68 270 bottom
R282  250  [R0402]  63.88 25.68 270 bottom
R283  0  [R0402]  98.17 12.19 90 bottom
R284  250  [R0402]  71.75 25.68 270 bottom
R285  0  [R0402]  95.63 12.19 90 bottom
R286  0  [R0402]  85.85 12.19 90 bottom
R287  0  [R0402]  79.88 12.32 90 bottom
R288  4.02K  [R0402]  28 13.26 180 bottom
R289  4.02K  [R0402]  25.85 13.26 180 bottom
R290  DNI_4.02K  [R0402]  5.97 15.88 270 bottom
R291  DNI_4.02K  [R0402]  5.97 18.41 90 bottom
R292  0  [R0201]  44.55 76.12 90 bottom
R293  DNI_0  [R0402]  7.87 15.88 270 bottom
R294  0  [R0201]  43.56 76.12 90 bottom
R295  DNI_0  [R0402]  7.87 18.41 90 bottom
R296  0  [R0402]  26.87 11.05 90 bottom
R297  0  [R0402]  25.84 11.05 90 bottom
R298  DNI_0  [R0402]  7.87 15.88 0 bottom
R299  DNI_0  [R0402]  7.87 18.41 0 bottom
R300  4.99K  [R0402]  74.04 13.46 270 bottom
R301  4.99K  [R0402]  69.98 13.46 270 bottom
R302  4.99K  [R0402]  68.71 13.46 270 bottom
R303  4.99K  [R0402]  67.44 13.46 270 bottom
R304  4.99K  [R0402]  66.17 13.46 270 bottom
R305  4.99K  [R0402]  32.13 8 90 bottom
R306  4.02K  [R0402]  23.62 5.74 180 bottom
R307  4.02K  [R0402]  23.63 4.74 180 bottom
R308  0  [R0402]  20.44 5.96 180 bottom
R309  0  [R0402]  17.02 5.97 0 bottom
R371  1.2K  [R0603]  119.98 135.61 180 bottom
R451  0  [R0201]  45.11 76.15 225 bottom
R459  0  [R0402]  119.13 18.29 180 bottom
R460  0  [R0402]  119.13 19.56 180 bottom
R461  0  [R0402]  119.13 20.83 180 bottom
R462  0  [R0402]  119.13 22.1 180 bottom
R463  0  [R0402]  119.13 23.37 180 bottom
R465  49.9K  [R0603]  80.77 111.12 180 bottom
R466  0  [R0402]  81.28 109.47 180 bottom
R472  DNI_4.99K  [R0402]  94.67 22.06 0 bottom
R473  DNI_4.99K  [R0402]  94.67 19.55 0 bottom
R476  DNI_2K  [R0402]  94.67 21.22 0 bottom
R477  DNI_2K  [R0402]  94.67 20.39 0 bottom
R486  0  [R0402]  71.63 107.57 180 bottom
R491  0  [R0201]  44.09 76.15 225 bottom
R496  DNI_150  [R0201]  32.34 94.26 0 bottom
R497  DNI_150  [R0201]  32 94.26 180 bottom
R498  DNI_150  [R0201]  20.62 89.28 0 bottom
R499  DNI_150  [R0201]  20.29 89.28 180 bottom
R508  0  [R0402]  81.92 34.73 270 bottom
R509  0  [R0402]  80.26 34.73 270 bottom
R510  0  [R0402]  83.57 34.73 270 bottom
R511  0  [R0402]  78.61 34.73 270 bottom
R532  0  [R0402]  84.33 12.19 90 bottom
R533  0  [R0402]  81.66 12.32 90 bottom
R538  100  [R0603]  44.8 26.34 270 bottom
R539  4.99K  [R0603]  46.7 15.61 90 top
R540  100  [R0603]  46.7 26.34 270 bottom
R541  100K  [R0603]  44.8 17.29 90 bottom
R542  0  [R0805]  27.3 41.78 90 bottom
R543  49.9  [R0603]  46.7 17.29 90 bottom
R544  0  [R0805]  20.95 26.67 270 bottom
R545  100  [R0603]  44.8 36.37 270 bottom
R546  100K  [R0402]  44.8 20.11 270 top
R547  100  [R0603]  46.7 36.37 270 bottom
R548  100K  [R0402]  46.7 20.11 270 top
R549  44.2K  [R0402]  44.8 30.14 270 top
R551  100  [R0402]  53.34 25.81 180 bottom
R553  44.2K  [R0402]  46.7 30.14 270 top
R556  4.99K  [R0402]  52.38 36 270 bottom
R557  4.99K  [R0402]  44.8 27.86 90 bottom
R558  4.99K  [R0402]  46.7 27.86 90 bottom
R559  4.99K  [R0402]  54.36 22.48 90 bottom
R560  4.99K  [R0402]  32.09 32.73 180 bottom
R561  4.99K  [R0402]  32.13 31.11 180 bottom
R562  4.99K  [R0402]  49.78 41.91 180 bottom
R563  4.99K  [R0402]  49.66 39.37 180 bottom
R564  4.99K  [R0402]  54.34 20.74 270 bottom
R565  0  [R0201]  79.02 53.49 120 top
R566  0  [R0201]  79.73 53.49 60 top
R567  0  [R0201]  89.18 53.49 120 top
R568  0  [R0201]  89.89 53.49 60 top
R569  0  [R0201]  94.26 53.49 120 top
R570  0  [R0201]  94.97 53.49 60 top
R571  0  [R0201]  104.42 53.49 120 top
R572  0  [R0201]  105.13 53.49 60 top
R573  0  [R0201]  105.13 72.24 300 top
R574  0  [R0201]  104.42 72.24 240 top
R575  0  [R0201]  94.97 72.24 300 top
R576  0  [R0201]  94.26 72.24 240 top
R577  0  [R0201]  89.89 72.24 300 top
R578  0  [R0201]  89.18 72.24 240 top
R579  0  [R0201]  79.73 72.24 300 top
R580  0  [R0201]  79.02 72.24 240 top
R581  0  [R0201]  8.81 85.6 180 top
R582  0  [R0201]  8.81 100.84 180 top
R600  88.7  [R0603]  95.5 42.04 270 bottom
R601  88.7  [R0603]  117.98 85.85 270 bottom
R602  4.99K  [R0603]  116.9 116.33 180 bottom
R603  1.13K  [R0603]  111.02 120.53 0 bottom
R604  4.02K  [R0603]  115.3 120.53 180 bottom
R605  88.7  [R0603]  115.32 123.19 270 bottom
R606  4.99K  [R0603]  117.54 35.43 180 bottom
R607  1.13K  [R0603]  111.66 39.63 0 bottom
R608  4.02K  [R0603]  115.94 39.63 180 bottom
R609  88.7  [R0603]  115.95 42.29 270 bottom
R610  3  [R0603]  67.94 171.45 270 bottom
R611  3  [R0603]  102.11 123.19 270 bottom
R612  47  [R0603]  92.2 146.56 180 bottom
R613  0  [R0603]  72.77 146.69 180 bottom
R614  4.99K  [R0402]  39.68 20.95 90 bottom
R615  DNI_4.99K  [R0402]  38.73 20.95 90 bottom
R616  250  [R0402]  38.73 11.81 0 bottom
R617  DNI_4.99K  [R0402]  108.2 13.08 90 bottom
R618  DNI_4.99K  [R0402]  109.6 13.08 90 bottom
R619  49.9K  [R0402]  84.33 9.53 90 bottom
R620  49.9K  [R0402]  81.66 9.53 90 bottom
R621  0  [R0402]  90.55 25.65 90 bottom
R622  0  [R0402]  91.69 25.65 90 bottom
R623  DNI_0  [R0402]  89.41 26.8 0 bottom
R624  DNI_0  [R0402]  92.84 26.8 180 bottom
R625  DNI_4.99K  [R0402]  121.67 18.54 90 top
R626  DNI_4.99K  [R0402]  123.06 18.54 90 top
R627  DNI_4.99K  [R0402]  121.67 23.5 270 top
R628  DNI_4.99K  [R0402]  123.06 23.5 270 top
R629  0  [R0402]  121.16 25.53 180 top
R630  0  [R0402]  121.16 26.67 180 top
R631  4.99K  [R0402]  118.49 25.53 180 top
R632  0  [R0402]  121.73 11.73 90 top
R633  0  [R0402]  117.35 26.67 0 top
R634  DNI_0  [R0402]  28.01 12.2 180 bottom
R635  DNI_0  [R0402]  24.69 12.2 0 bottom
R636  DNI_0  [R0402]  18.16 7.11 270 bottom
R637  DNI_0  [R0402]  19.3 7.11 270 bottom
R638  DNI_4.99K  [0402]  32.13 5.21 90 bottom
R639  DNI_0  [0603]  15.11 7.11 180 bottom
R640  DNI_0  [0603]  13.46 5.21 0 bottom
R641  100  [0402]  16.13 21.34 0 bottom
R642  4.99K  [0402]  22.62 20.99 90 bottom
R643  49.9K  [0402]  30.51 23.24 180 bottom
R644  100  [0402]  2.16 22.86 90 bottom
R645  4.99K  [0402]  13.72 21.84 180 bottom
R646  49.9K  [0402]  13.49 24.64 180 bottom
R647  DNI_4.99K  [0402]  53.21 11.56 90 bottom
R648  4.99K  [0402]  94.36 23.5 0 bottom
R649  DNI_0  [R0402]  85.34 34.73 270 bottom
R650  DNI_0  [R0402]  76.95 34.73 270 bottom
R651  0  [0402]  81.92 40.51 270 bottom
R652  0  [0402]  80.26 40.51 270 bottom
R653  0  [0402]  83.57 40.51 270 bottom
R654  0  [0402]  78.61 40.51 270 bottom
R655  0  [0402]  85.34 40.51 270 bottom
R656  0  [0402]  76.96 40.51 270 bottom
R657  DNI_4.99K  [0402]  87.12 40.51 270 bottom
R658  DNI_4.99K  [0402]  75.18 40.51 270 bottom
R659  0  [0402]  81.92 43.81 270 bottom
R660  0  [0402]  80.26 43.81 270 bottom
R661  0  [0402]  83.57 43.81 270 bottom
R662  0  [0402]  78.61 43.81 270 bottom
R663  0  [0402]  85.34 43.81 270 bottom
R664  0  [0402]  76.96 43.81 270 bottom
R665  83  [R0201]  24.51 135.39 0 bottom
R666  83  [R0201]  26.13 135.39 180 bottom
R667  130  [R0201]  24.51 134.71 0 bottom
R668  130  [R0201]  26.13 134.71 180 bottom
R669  4.99K  [0402]  20.95 133.52 90 bottom
R670  83  [R0201]  20.62 130.39 90 bottom
R671  83  [R0201]  20.62 132.02 270 bottom
R672  130  [R0201]  21.26 130.95 270 bottom
R673  130  [R0201]  21.26 131.46 90 bottom
R674  DNI_150  [R0201]  19.1 130.95 270 bottom
R675  DNI_150  [R0201]  19.1 131.46 90 bottom
R676  150  [R0201]  29.39 131.96 90 bottom
R677  150  [R0201]  29.39 131.58 270 bottom
R678  150  [R0201]  29.39 130.06 90 bottom
R679  150  [R0201]  29.39 129.68 270 bottom
R680  150  [R0201]  26.59 126.76 0 bottom
R681  150  [R0201]  26.21 126.76 180 bottom
R682  150  [R0201]  24.69 126.76 0 bottom
R683  150  [R0201]  24.31 126.76 180 bottom
R684  83  [R0201]  21.08 164.77 270 top
R685  83  [R0201]  21.08 163.15 90 top
R686  130  [R0201]  21.72 164.21 90 top
R687  130  [R0201]  21.72 163.7 270 top
R688  4.99K  [0402]  22.95 168.32 180 top
R689  83  [R0201]  26.09 168.66 180 top
R690  83  [R0201]  24.46 168.66 0 top
R691  130  [R0201]  25.53 168.02 0 top
R692  130  [R0201]  25.02 168.02 180 top
R693  DNI_150  [R0201]  25.53 170.18 0 top
R694  DNI_150  [R0201]  25.02 170.18 180 top
R695  150  [R0201]  24.51 159.89 180 top
R696  150  [R0201]  24.89 159.89 0 top
R697  150  [R0201]  26.42 159.89 180 top
R698  150  [R0201]  26.8 159.89 0 top
R699  150  [R0201]  29.72 162.69 270 top
R700  150  [R0201]  29.72 163.07 90 top
R701  150  [R0201]  29.72 164.59 270 top
R702  150  [R0201]  29.72 164.97 90 top
R703  400  [R0402]  18.8 149.99 90 top
R704  0  [R0402]  16.38 149.86 90 top
R705  250  [R0402]  21.94 113.89 0 bottom
R706  4.99K  [R0402]  21.3 109.59 270 bottom
R707  4.99K  [R0402]  21.3 105.4 90 bottom
R708  100K  [R0402]  19.12 106.54 0 bottom
R709  100K  [R0402]  19.12 108.44 0 bottom
R710  250  [R0402]  13.55 106.54 270 bottom
R711  250  [R0402]  13.55 108.44 90 bottom
R712  0  [R0603]  15.24 149.86 90 top
R713  0  [R0603]  17.53 149.86 90 top
R714  4.99K  [R0402]  11.43 148.53 270 bottom
R715  4.99K  [R0402]  12.7 148.53 270 bottom
R716  4.99K  [R0402]  14.99 156.58 270 bottom
R717  4.99K  [R0402]  17.65 156.58 270 bottom
R718  4.99K  [R0603]  16.38 157.1 270 bottom
R719  4.99K  [R0603]  18.8 157.1 270 bottom
R720  0  [R0402]  1.4 167.26 270 bottom
R721  0  [R0402]  2.67 167.26 270 bottom
R722  0  [R0402]  3.94 167.26 270 bottom
R723  0  [R0603]  55.87 119.41 270 bottom
R724  DNI_4.99K  [R0603]  57.02 117.73 90 bottom
R725  4.99K  [R0603]  58.18 117.73 90 bottom
R726  DNI_0  [R0402]  59.18 112.27 270 bottom
R727  0  [R0402]  57.91 112.27 270 bottom
R728  49.9  [R0603]  68.04 110.47 180 bottom
R729  100K  [R0603]  68.04 112.38 180 bottom
R730  100K  [R0402]  66.92 105.9 0 bottom
R731  100K  [R0402]  66.92 107.8 0 bottom
R732  100  [R0603]  61.35 104.22 90 bottom
R733  100  [R0603]  61.35 109.48 270 bottom
R734  4.99K  [R0603]  45.45 112.39 270 bottom
R735  0  [R0603]  44.31 112.39 270 bottom
R736  49.9  [R0603]  52.55 110.6 180 bottom
R737  100K  [R0603]  52.55 112.5 180 bottom
R738  100K  [R0402]  51.42 106.03 0 bottom
R739  100K  [R0402]  51.42 107.93 0 bottom
R740  100  [R0603]  45.85 104.35 90 bottom
R741  100  [R0603]  45.85 109.6 270 bottom
R742  4.99K  [R0603]  31.36 112.65 270 bottom
R743  0  [R0603]  30.21 112.65 270 bottom
R744  49.9  [R0603]  38.45 110.85 180 bottom
R745  100K  [R0603]  38.45 112.76 180 bottom
R746  100K  [R0402]  37.33 106.28 0 bottom
R747  100K  [R0402]  37.33 108.18 0 bottom
R748  100  [R0603]  31.75 104.61 90 bottom
R749  100  [R0603]  31.75 109.86 270 bottom
R750  4.99K  [R0402]  12.33 115.23 180 bottom
R751  4.99K  [R0402]  12.32 117.73 180 bottom
R752  4.99K  [R0402]  8.27 129.45 270 bottom
R753  4.99K  [R0402]  10.41 119.16 90 bottom
R754  0  [R0402]  9.16 115.23 0 bottom
R755  0  [R0402]  9.16 117.73 0 bottom
R756  0  [R0402]  9.31 120.31 270 bottom
R757  0  [R0402]  9.27 122.8 270 bottom
R758  DNI_0  [R0402]  8.27 126.28 90 bottom
R759  DNI_0  [R0402]  6.24 112.69 0 bottom
R760  DNI_0  [R0402]  6.24 115.23 0 bottom
R761  DNI_0  [R0402]  6.24 117.77 0 bottom
R762  DNI_0  [R0402]  6.24 120.31 0 bottom
R763  DNI_0  [R0402]  6.24 122.85 0 bottom
R764  DNI_0  [R0402]  6.24 125.39 0 bottom
R765  0  [R0402]  8.27 114.08 90 bottom
R766  0  [R0402]  8.26 116.59 90 bottom
R767  0  [R0402]  8.27 119.16 90 bottom
R768  0  [R0402]  8.26 121.67 90 bottom
R769  0  [R0402]  8.27 124.24 90 bottom
R770  0  [R0402]  9.21 167.94 270 bottom
R771  0  [R0402]  13.21 163.58 270 bottom
R772  DNI_4.99K  [R0402]  10.22 166.8 90 bottom
R773  DNI_4.99K  [R0402]  8.13 167.96 270 bottom
R774  DNI_4.99K  [R0402]  12.08 162.45 90 bottom
R775  DNI_4.99K  [R0402]  14.34 161.18 180 bottom
R776  250  [R0402]  9.02 161.35 270 bottom
R777  0  [R0201]  10.84 143.06 270 top
R778  5.49K  [R0201]  12.19 140.46 0 bottom
R779  3.16K  [R0201]  11.18 140.46 0 bottom
R780  DNI_49.9  [R0201]  12.74 143.06 270 top
R781  DNI_49.9  [R0201]  12.74 141.44 90 top
R782  DNI_150  [R0201]  4.19 143.89 0 top
R783  DNI_150  [R0201]  4.19 140.59 0 top
R784  DNI_0  [R0201]  10.84 142.5 180 top
R785  DNI_0  [R0201]  10.84 142 180 top
R786  4.99K  [R0402]  7.11 166.81 90 bottom
R787  4.99K  [R0402]  12.45 166.8 90 bottom
R788  0  [R0402]  14.41 129.24 90 bottom
R789  0  [R0402]  10.41 133.6 90 bottom
R790  DNI_4.99K  [R0402]  13.53 130.38 270 bottom
R791  DNI_4.99K  [R0402]  15.37 129.22 90 bottom
R792  250  [R0402]  14.61 135.83 90 bottom
R793  DNI_4.99K  [R0402]  11.55 134.73 270 bottom
R794  DNI_4.99K  [R0402]  9.28 136 0 bottom
R795  DNI_4.99K  [R0402]  27.26 32.73 180 bottom
R796  DNI_4.99K  [R0402]  27.26 31.11 180 bottom
SW10  B3U-1100P  [OMRON_3PIN_US_B3U-1100P]  82.8 113.54 0 top
SW11  Rocker Switch 10 position  [GDH10S_THOMASBETTS]  106.3 4.83 0 top
SW12  Rocker Switch 4 position  [GDH04S_THOMASBETTS]  66.8 4.83 0 top
SW13  B3U-1100P  [OMRON_3PIN_US_B3U-1100P]  63.63 115.7 0 top
SW14  B3U-1100P  [OMRON_3PIN_US_B3U-1100P]  48.13 115.82 0 top
SW15  B3U-1100P  [OMRON_3PIN_US_B3U-1100P]  34.04 116.08 0 top
SW16  Rocker Switch 4 position  [GDH04S_THOMASBETTS]  2.03 160.4 0 top
SW17  Rocker Switch 8 position  [GDH08S_THOMASBETTS]  109.09 135.25 180 top
SW18  Rocker Switch 2 position  [GDH02S_THOMASBETTS]  26.42 118.11 270 top
SW19  Rocker Switch 2 position  [GDH02S_THOMASBETTS]  18.41 115.57 0 top
TH1  Header 1x1  [THERMAL_HOLE]  87.5 36.45 90 top
TH2  Header 1x1  [THERMAL_HOLE]  98.04 39.88 90 top
TH3  Header 1x1  [THERMAL_HOLE]  120.52 83.69 90 top
TH4  Header 1x1  [THERMAL_HOLE]  109.98 80.26 90 top
TH5  Header 1x1  [THERMAL_HOLE]  117.86 121.03 90 top
TH6  Header 1x1  [THERMAL_HOLE]  107.31 117.6 90 top
TH7  Header 1x1  [THERMAL_HOLE]  107.95 36.7 90 top
TH8  Header 1x1  [THERMAL_HOLE]  118.49 40.13 90 top
TH9  Header 1x1  [THERMAL_HOLE]  70.48 169.29 90 top
TH10  Header 1x1  [THERMAL_HOLE]  59.94 165.86 90 top
TH11  Header 1x1  [THERMAL_HOLE]  104.65 121.03 90 top
TH12  Header 1x1  [THERMAL_HOLE]  94.11 117.6 90 top
TH13  Header 1x1  [THERMAL_HOLE]  86.23 154.69 0 top
TH14  Header 1x1  [THERMAL_HOLE]  89.66 144.15 0 top
TH15  Header 1x1  [THERMAL_HOLE]  67.18 154.69 0 top
TH16  Header 1x1  [THERMAL_HOLE]  70.61 144.15 0 top
U1  TLK10081  [ZWQ144]  45.59 73.66 180 top
U8  TPS74401RGW  [RGW20]  92.51 36.47 0 top
U10  TPS74401RGW  [RGW20]  114.99 80.29 0 top
U12  TPS74401RGW  [RGW20]  86.26 149.68 270 top
U16  TPS74401RGW  [RGW20]  67.21 149.68 270 top
U22  TPS74401RGW  [RGW20]  99.12 117.63 0 top
U24  TPS74401RGW  [RGW20]  64.95 165.89 0 top
U36  SN74AVCH1T45DBV  [DCK6]  73.8 103.09 90 bottom
U37  TPS3125J18  [SOT23_5PIN]  77.54 108.52 0 bottom
U38  ZXTD09N50DE6  [DDC6]  76.45 113.41 270 bottom
U40  TXB0108PWR  [PW20]  53.27 11.81 270 top
U41  TXB0108PWR  [PW20]  86.11 20.9 0 top
U42  TCA6424  [RGJ32]  100.07 21.35 90 top
U43  TXS0108EPWR  [PW20]  27.72 6.22 270 bottom
U64  TXB0108PWR  [PW20]  112.27 21.28 180 top
U92  TPS3125J18  [SOT23_5PIN]  51.44 32.26 90 top
U93  ZXTD09N50DE6  [DDC6]  45.75 21.46 270 bottom
U94  ZXTD09N50DE6  [DDC6]  45.75 31.5 270 bottom
U100  CDCM6208  [HQFN_48_282X282_20]  18.16 143.25 270 top
U101  TPS74401RGW  [RGW20]  112.32 117.63 0 top
U102  TPS74401RGW  [RGW20]  112.96 36.73 0 top
U103  TLV70225  [SOT23_5PIN]  38.73 18.03 270 bottom
U104  CDCLVP1204  [QFN50P300X300X100-16]  25.32 130.69 90 bottom
U105  CDCLVP1204  [QFN50P300X300X100-16]  25.78 163.96 180 top
U106  ZXTD09N50DE6  [DDC6]  16.75 107.49 0 bottom
U107  SN74LVC1G08-Q1DBV  [DBV]  56.91 115.07 0 bottom
U108  TPS3125J18  [SOT23_5PIN]  63.75 111.39 180 top
U109  ZXTD09N50DE6  [DDC6]  64.55 106.85 0 bottom
U110  TPS3125J18  [SOT23_5PIN]  48.26 111.52 180 top
U111  ZXTD09N50DE6  [DDC6]  49.05 106.98 0 bottom
U112  TPS3125J18  [SOT23_5PIN]  34.16 111.77 180 top
U113  ZXTD09N50DE6  [DDC6]  34.96 107.23 0 bottom
U114  TLV70233  [SOT23_5PIN]  10.16 164.08 270 top
U115  TLV70233  [SOT23_5PIN]  13.46 133.1 90 top
Y10  NZ2016SA_30.72MHz  [NZ2016SA-ICXO]  11.58 160.53 270 bottom
Y11  NZ2016SA_31.25MHz  [NZ2016SA-ICXO]  12.05 136.65 90 bottom

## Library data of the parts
C15 C16 C19 C21-C23 C26 C28-C31 C35 C43-C45 C49 C64-C66 C70-C73 C77 C80 C84 C93 C97 C107 C108 C117 C118 C127 C137 C189 C190 C274 C275 C278-C283 C286 C298 C302-C304 C600-C603 C607-C610 C616 C618 C620 C622 C624 C626 C628 C630 C634 C685 = CAP NP
C17 C18 C20 C24 C25 C27 C32-C34 C46-C48 C67-C69 C74-C76 C85 C89 C94 C99 C109 C113 C119 C123 C128 C136 C138 C604-C606 C611-C613 C631 C635 = NPCap1206_1.0uf
C86 C90 C95 C100 C110 C114 C120 C124 C129 C139 C632 C636 = NPCap1206_0.1uf
C87 C91 C98 C101 C111 C115 C121 C125 C130 C140 C633 C637 = NPCap0805_0.01uf
C141-C153 C163-C174 C188 C191-C206 C210-C225 C247 C249 C295 C297 C299 C301 C614 C615 C617 C619 C621 C623 C625 C627 C629 C638-C684 C686-C695 = cc0402
C296 C300 = cc0805
D9 = BAT60A
D10 D12 D13 D50 D51 D105 D107 D109 = LED_HSMS
D11 D14-D16 D49 D100-D102 D104 D106 D108 D110 = LED_HSMG
D28 = LED_HSMB
D48 D111 = LED_HSMD
D52 D103 = LED_HSMY
J5-J8 = Edge Launch SMA_0
J41-J48 J103 J104 = sma_surface
J72 J102 = SEAF_ASP-134486-01_0
J73 = SFP_PLUS_CONN_WITH_CAGE
J100 = MEC1-130-02-F-D-A Connector
J101 = MEC1-120-02-F-D-A Connector
JMP35 JMP41 JMP42 = 3 Pin Berg Jumper
JMP36 JMP100 = 2 Pin Berg Jumper
JMP47 JMP48 = Header 5x2
JMP50 JMP103 JMP105 = Header 2x2
JMP61 = Header 4x2
JMP62 = 3 Pin Berg Jumper Single Side
JMP77 = Header T 4pin
JMP101 = 2 Pin Berg Jumper Straight
JMP102 JMP104 = Header 6x2
K1-K4 = AQY221R2T
L1-L9 L14 = Ferrite Bead_1206
L15 L16 = Inductor_1210
L100-L106 = INDUCTOR_0
P1 P14 = Banana-Jack: User Part Number: 3267
P26 = RAPC722
Q3-Q7 Q11 Q12 Q100-Q106 = FDV301N_NFET_1
R49 R50 R52 R66 R67 R69 R83 R84 R86 R117 R118 R120 R168 R169 R171 R185 R186 R188 R239 R241-R244 R246 R268 R269 R288-R295 R305-R307 R371 R465 R538-R541 R543 R545 R547 R600-R613 R621-R635 R638 R641 R644 R647 R648 R669 R688 = r0603
R240 R245 R247-R259 R262 R263 R270 R273-R287 R300-R304 R459-R463 R466 R472 R473 R476 R477 R486 R496-R499 R508-R511 R532 R533 R542 R544 R546 R548 R549 R551 R553 R556-R564 R614-R620 R642 R643 R645 R646 R649-R668 R670-R687 R689-R796 = r0402
R296-R299 R308 R309 R451 R491 R565-R582 R636 R637 R639 R640 = r0201
SW10 SW13-SW15 = B3U-1100P
SW11 = Rocker Switch 10 position_0
SW12 SW16 = Rocker Switch 4 position_0
SW17 = Rocker Switch 8 position_1
SW18 SW19 = Rocker Switch 2 position
TH1-TH16 = Header 1x1_0
U1 = TLK10081
U8 U10 U12 U16 U22 U24 U101 U102 = TPS74x01RGW_0
U36 = SN74AVCH1T45DBV
U37 U92 = TPS3125J18_0
U38 U93 U94 U106 U109 U111 U113 = ZXTD09N50DE6
U40 U41 U64 = TXB0108PWR
U42 = TCA6424_0
U43 = TXS0108EPWR
U100 = CDCM6208
U103 U114 U115 = TLV713
U104 U105 = CDCLVP1204
U107 = SN74LVC1G08-Q1DBV
U108 U110 U112 = TPS3125J18
Y10 = NZ2016SA_30.72MHz
Y11 = NZ2016SA_31.25MHz

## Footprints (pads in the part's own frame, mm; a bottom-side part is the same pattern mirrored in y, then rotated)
32K141-40M-FR4WVIA
  rect 0.8x2.2 smd: 1(0,-3.1)
  round 1.626 hole 1.118: 2(2.54,2.54) 3(2.54,-2.54) 4(-2.54,2.54) 5(-2.54,-2.54)
0402
  rect 0.7x0.9 smd: 1(0,0) 2(1.3,0)
0603
  rect 1x1.1 smd: 1(0,0) 2(1.7,0)
0805
  rect 1.3x1.5 smd: 1(0,0) 2(1.9,0)
1210
  rect 1.27x2.54 smd: 1(-1.524,0) 2(1.524,0)
AMP_SFPCAGE_WIDECHANNEL
  round 0 hole 1.55 unplated: (0.889,-4.804) (0.899,4.786)
  rect 2x0.5 smd: 1(-3.211,3.395) 2(-3.211,2.596) 3(-3.211,1.796) 4(-3.211,0.996) 5(-3.211,0.196) 6(-3.211,-0.605) 7(-3.211,-1.404) 8(-3.211,-2.204) 9(-3.211,-3.005) 10(-3.211,-3.804) 11(4.979,-3.404) 12(4.979,-2.605) 13(4.979,-1.804) 14(4.979,-1.004) 15(4.979,-0.204) 16(4.979,0.596) 17(4.979,1.395) 18(4.979,2.196) 19(4.979,2.996) 20(4.979,3.796)
  round 0.95 hole 0.95: 21(7.1,4.8) 22(2.5,7.125) 24(-2.5,7.125) 25(-7.2,7.125) 34(-7.2,-7.125) 36(-2.5,-7.125) 37(2.5,-7.125) 39(7.1,-4.8) 40(7.1,0)
  rect 2x2 hole 0.85: 23(0,7.125)
  rect 2x2 hole 1.05: 26(-10,7.125) 27(-10,1.445) 28(-20,7.125) 29(-30,7.125) 30(-30,-1.455) 31(-25,-7.125) 32(-15,-7.125) 33(-10,-3.955) 35(-5,-7.125) 38(5,-7.125)
ASP-134486
  round 0.635 hole 1.27 unplated: (-27.178,0) (27.178,-3.048)
  round 6.604 hole 3.302 unplated: (-24.765,31.115) (-24.765,-27.305) (24.765,31.115) (24.765,-27.305)
  round 0.635 smd: A1(24.765,-5.715) A2(23.495,-5.715) A3(22.225,-5.715) A4(20.955,-5.715) A5(19.685,-5.715) A6(18.415,-5.715) A7(17.145,-5.715) A8(15.875,-5.715) A9(14.605,-5.715) A10(13.335,-5.715) A11(12.065,-5.715) A12(10.795,-5.715) A13(9.525,-5.715) A14(8.255,-5.715) A15(6.985,-5.715) A16(5.715,-5.715) A17(4.445,-5.715) A18(3.175,-5.715) A19(1.905,-5.715) A20(0.635,-5.715) A21(-0.635,-5.715) A22(-1.905,-5.715) A23(-3.175,-5.715) A24(-4.445,-5.715) A25(-5.715,-5.715) A26(-6.985,-5.715) A27(-8.255,-5.715) A28(-9.525,-5.715) A29(-10.795,-5.715) A30(-12.065,-5.715) A31(-13.335,-5.715) A32(-14.605,-5.715) A33(-15.875,-5.715) A34(-17.145,-5.715) A35(-18.415,-5.715) A36(-19.685,-5.715) A37(-20.955,-5.715) A38(-22.225,-5.715) A39(-23.495,-5.715) A40(-24.765,-5.715) B1(24.765,-4.445) B2(23.495,-4.445) B3(22.225,-4.445) B4(20.955,-4.445) B5(19.685,-4.445) B6(18.415,-4.445) B7(17.145,-4.445) B8(15.875,-4.445) B9(14.605,-4.445) B10(13.335,-4.445) B11(12.065,-4.445) B12(10.795,-4.445) B13(9.525,-4.445) B14(8.255,-4.445) B15(6.985,-4.445) B16(5.715,-4.445) B17(4.445,-4.445) B18(3.175,-4.445) B19(1.905,-4.445) B20(0.635,-4.445) B21(-0.635,-4.445) B22(-1.905,-4.445) B23(-3.175,-4.445) B24(-4.445,-4.445) B25(-5.715,-4.445) B26(-6.985,-4.445) B27(-8.255,-4.445) B28(-9.525,-4.445) B29(-10.795,-4.445) B30(-12.065,-4.445) B31(-13.335,-4.445) B32(-14.605,-4.445) B33(-15.875,-4.445) B34(-17.145,-4.445) B35(-18.415,-4.445) B36(-19.685,-4.445) B37(-20.955,-4.445) B38(-22.225,-4.445) B39(-23.495,-4.445) B40(-24.765,-4.445) C1(24.765,-3.175) C2(23.495,-3.175) C3(22.225,-3.175) C4(20.955,-3.175) C5(19.685,-3.175) C6(18.415,-3.175) C7(17.145,-3.175) C8(15.875,-3.175) C9(14.605,-3.175) C10(13.335,-3.175) C11(12.065,-3.175) C12(10.795,-3.175) C13(9.525,-3.175) C14(8.255,-3.175) C15(6.985,-3.175) C16(5.715,-3.175) C17(4.445,-3.175) C18(3.175,-3.175) C19(1.905,-3.175) C20(0.635,-3.175) C21(-0.635,-3.175) C22(-1.905,-3.175) C23(-3.175,-3.175) C24(-4.445,-3.175) C25(-5.715,-3.175) C26(-6.985,-3.175) C27(-8.255,-3.175) C28(-9.525,-3.175) C29(-10.795,-3.175) C30(-12.065,-3.175) C31(-13.335,-3.175) C32(-14.605,-3.175) C33(-15.875,-3.175) C34(-17.145,-3.175) C35(-18.415,-3.175) C36(-19.685,-3.175) C37(-20.955,-3.175) C38(-22.225,-3.175) C39(-23.495,-3.175) C40(-24.765,-3.175) D1(24.765,-1.905) D2(23.495,-1.905) D3(22.225,-1.905) D4(20.955,-1.905) D5(19.685,-1.905) D6(18.415,-1.905) D7(17.145,-1.905) D8(15.875,-1.905) D9(14.605,-1.905) D10(13.335,-1.905) D11(12.065,-1.905) D12(10.795,-1.905) D13(9.525,-1.905) D14(8.255,-1.905) D15(6.985,-1.905) D16(5.715,-1.905) D17(4.445,-1.905) D18(3.175,-1.905) D19(1.905,-1.905) D20(0.635,-1.905) D21(-0.635,-1.905) D22(-1.905,-1.905) D23(-3.175,-1.905) D24(-4.445,-1.905) D25(-5.715,-1.905) D26(-6.985,-1.905) D27(-8.255,-1.905) D28(-9.525,-1.905) D29(-10.795,-1.905) D30(-12.065,-1.905) D31(-13.335,-1.905) D32(-14.605,-1.905) D33(-15.875,-1.905) D34(-17.145,-1.905) D35(-18.415,-1.905) D36(-19.685,-1.905) D37(-20.955,-1.905) D38(-22.225,-1.905) D39(-23.495,-1.905) D40(-24.765,-1.905) E1(24.765,-0.635) E2(23.495,-0.635) E3(22.225,-0.635) E4(20.955,-0.635) E5(19.685,-0.635) E6(18.415,-0.635) E7(17.145,-0.635) E8(15.875,-0.635) E9(14.605,-0.635) E10(13.335,-0.635) E11(12.065,-0.635) E12(10.795,-0.635) E13(9.525,-0.635) E14(8.255,-0.635) E15(6.985,-0.635) E16(5.715,-0.635) E17(4.445,-0.635) E18(3.175,-0.635) E19(1.905,-0.635) E20(0.635,-0.635) E21(-0.635,-0.635) E22(-1.905,-0.635) E23(-3.175,-0.635) E24(-4.445,-0.635) E25(-5.715,-0.635) E26(-6.985,-0.635) E27(-8.255,-0.635) E28(-9.525,-0.635) E29(-10.795,-0.635) E30(-12.065,-0.635) E31(-13.335,-0.635) E32(-14.605,-0.635) E33(-15.875,-0.635) E34(-17.145,-0.635) E35(-18.415,-0.635) E36(-19.685,-0.635) E37(-20.955,-0.635) E38(-22.225,-0.635) E39(-23.495,-0.635) E40(-24.765,-0.635) F1(24.765,0.635) F2(23.495,0.635) F3(22.225,0.635) F4(20.955,0.635) F5(19.685,0.635) F6(18.415,0.635) F7(17.145,0.635) F8(15.875,0.635) F9(14.605,0.635) F10(13.335,0.635) F11(12.065,0.635) F12(10.795,0.635) F13(9.525,0.635) F14(8.255,0.635) F15(6.985,0.635) F16(5.715,0.635) F17(4.445,0.635) F18(3.175,0.635) F19(1.905,0.635) F20(0.635,0.635) F21(-0.635,0.635) F22(-1.905,0.635) F23(-3.175,0.635) F24(-4.445,0.635) F25(-5.715,0.635) F26(-6.985,0.635) F27(-8.255,0.635) F28(-9.525,0.635) F29(-10.795,0.635) F30(-12.065,0.635) F31(-13.335,0.635) F32(-14.605,0.635) F33(-15.875,0.635) F34(-17.145,0.635) F35(-18.415,0.635) F36(-19.685,0.635) F37(-20.955,0.635) F38(-22.225,0.635) F39(-23.495,0.635) F40(-24.765,0.635) G1(24.765,1.905) G2(23.495,1.905) G3(22.225,1.905) G4(20.955,1.905) G5(19.685,1.905) G6(18.415,1.905) G7(17.145,1.905) G8(15.875,1.905) G9(14.605,1.905) G10(13.335,1.905) G11(12.065,1.905) G12(10.795,1.905) G13(9.525,1.905) G14(8.255,1.905) G15(6.985,1.905) G16(5.715,1.905) G17(4.445,1.905) G18(3.175,1.905) G19(1.905,1.905) G20(0.635,1.905) G21(-0.635,1.905) G22(-1.905,1.905) G23(-3.175,1.905) G24(-4.445,1.905) G25(-5.715,1.905) G26(-6.985,1.905) G27(-8.255,1.905) G28(-9.525,1.905) G29(-10.795,1.905) G30(-12.065,1.905) G31(-13.335,1.905) G32(-14.605,1.905) G33(-15.875,1.905) G34(-17.145,1.905) G35(-18.415,1.905) G36(-19.685,1.905) G37(-20.955,1.905) G38(-22.225,1.905) G39(-23.495,1.905) G40(-24.765,1.905) H1(24.765,3.175) H2(23.495,3.175) H3(22.225,3.175) H4(20.955,3.175) H5(19.685,3.175) H6(18.415,3.175) H7(17.145,3.175) H8(15.875,3.175) H9(14.605,3.175) H10(13.335,3.175) H11(12.065,3.175) H12(10.795,3.175) H13(9.525,3.175) H14(8.255,3.175) H15(6.985,3.175) H16(5.715,3.175) H17(4.445,3.175) H18(3.175,3.175) H19(1.905,3.175) H20(0.635,3.175) H21(-0.635,3.175) H22(-1.905,3.175) H23(-3.175,3.175) H24(-4.445,3.175) H25(-5.715,3.175) H26(-6.985,3.175) H27(-8.255,3.175) H28(-9.525,3.175) H29(-10.795,3.175) H30(-12.065,3.175) H31(-13.335,3.175) H32(-14.605,3.175) H33(-15.875,3.175) H34(-17.145,3.175) H35(-18.415,3.175) H36(-19.685,3.175) H37(-20.955,3.175) H38(-22.225,3.175) H39(-23.495,3.175) H40(-24.765,3.175) J1(24.765,4.445) J2(23.495,4.445) J3(22.225,4.445) J4(20.955,4.445) J5(19.685,4.445) J6(18.415,4.445) J7(17.145,4.445) J8(15.875,4.445) J9(14.605,4.445) J10(13.335,4.445) J11(12.065,4.445) J12(10.795,4.445) J13(9.525,4.445) J14(8.255,4.445) J15(6.985,4.445) J16(5.715,4.445) J17(4.445,4.445) J18(3.175,4.445) J19(1.905,4.445) J20(0.635,4.445) J21(-0.635,4.445) J22(-1.905,4.445) J23(-3.175,4.445) J24(-4.445,4.445) J25(-5.715,4.445) J26(-6.985,4.445) J27(-8.255,4.445) J28(-9.525,4.445) J29(-10.795,4.445) J30(-12.065,4.445) J31(-13.335,4.445) J32(-14.605,4.445) J33(-15.875,4.445) J34(-17.145,4.445) J35(-18.415,4.445) J36(-19.685,4.445) J37(-20.955,4.445) J38(-22.225,4.445) J39(-23.495,4.445) J40(-24.765,4.445) K1(24.765,5.715) K2(23.495,5.715) K3(22.225,5.715) K4(20.955,5.715) K5(19.685,5.715) K6(18.415,5.715) K7(17.145,5.715) K8(15.875,5.715) K9(14.605,5.715) K10(13.335,5.715) K11(12.065,5.715) K12(10.795,5.715) K13(9.525,5.715) K14(8.255,5.715) K15(6.985,5.715) K16(5.715,5.715) K17(4.445,5.715) K18(3.175,5.715) K19(1.905,5.715) K20(0.635,5.715) K21(-0.635,5.715) K22(-1.905,5.715) K23(-3.175,5.715) K24(-4.445,5.715) K25(-5.715,5.715) K26(-6.985,5.715) K27(-8.255,5.715) K28(-9.525,5.715) K29(-10.795,5.715) K30(-12.065,5.715) K31(-13.335,5.715) K32(-14.605,5.715) K33(-15.875,5.715) K34(-17.145,5.715) K35(-18.415,5.715) K36(-19.685,5.715) K37(-20.955,5.715) K38(-22.225,5.715) K39(-23.495,5.715) K40(-24.765,5.715)
BERG2
  rect 1.524x1.524 hole 0.965: 1(0,0)
  round 1.524 hole 0.965: 2(0,-2.54)
BERG2X2
  rect 1.524x1.524 hole 0.965: 1(0,0)
  round 1.524 hole 0.965: 2(2.54,0) 3(0,-2.54) 4(2.54,-2.54)
